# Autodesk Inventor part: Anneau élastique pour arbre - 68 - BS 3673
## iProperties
Shininess: 64.0
Length Units: 11269
Angle Units: 11279
Time Units: 11290
Mass Units: 11283
Length Display Precision: 3
Angle Display Precision: 2
Compacted: True
Part Number: Anneau élastique pour arbre - 68 - BS 3673
Document SubType Name: Modeling
Created: 2005-02
Material: Par défaut
Designer: LEGERET Philippe
Catalog Web Link: www.traceparts.com
Description: Anneau élastique pour arbre Ø68 - BS 3673
Density: 0.0
Volumn: 0.0
Area: 0.0
PropertySet Name: Model Information
Control State: 0
Master: False
Checked Out: False
Author: Trace Parts S.A.
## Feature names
1. Base1
